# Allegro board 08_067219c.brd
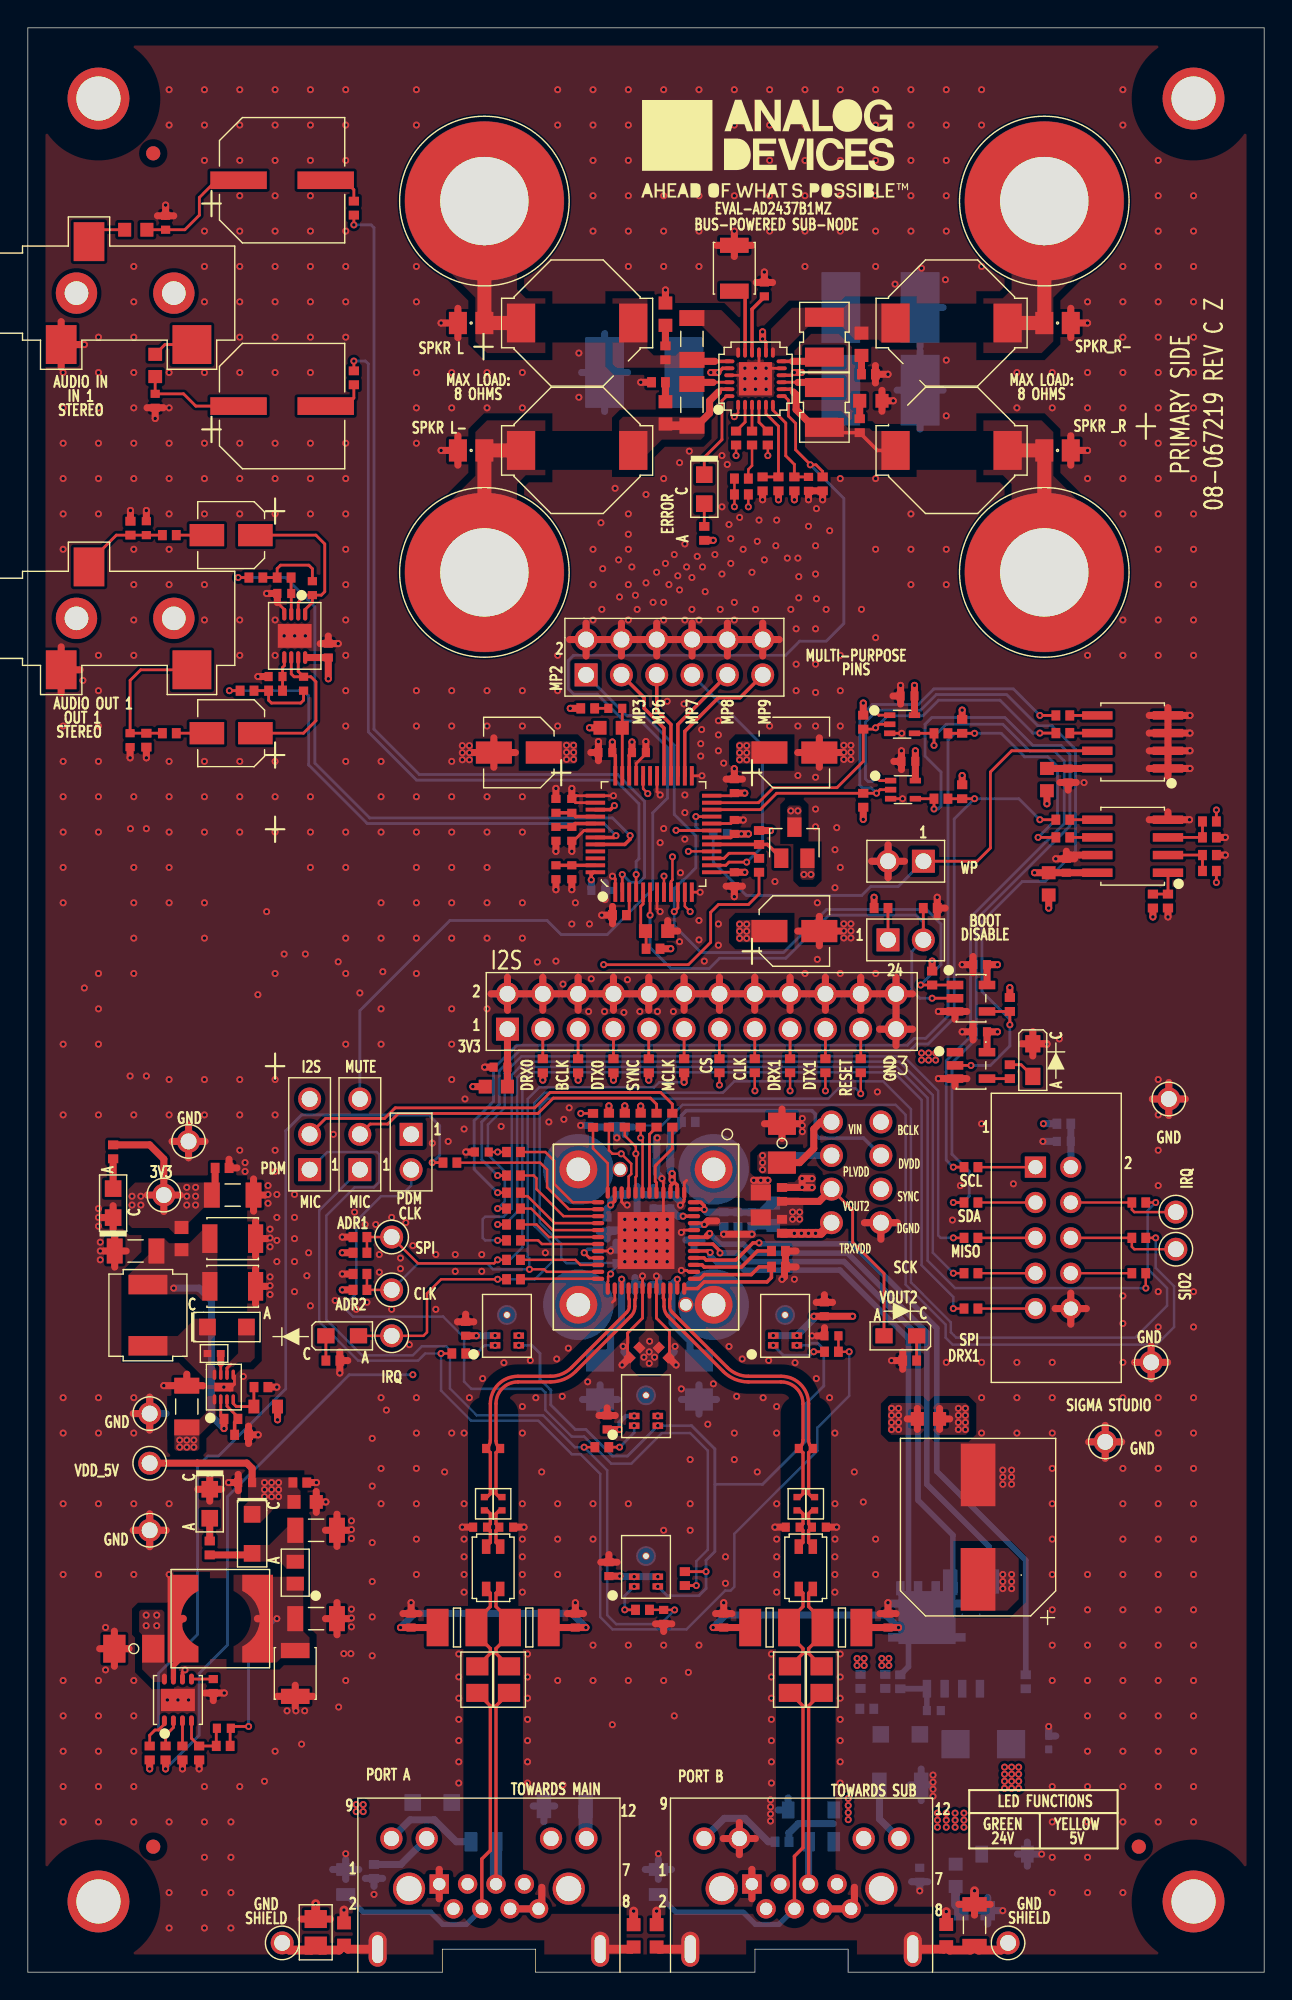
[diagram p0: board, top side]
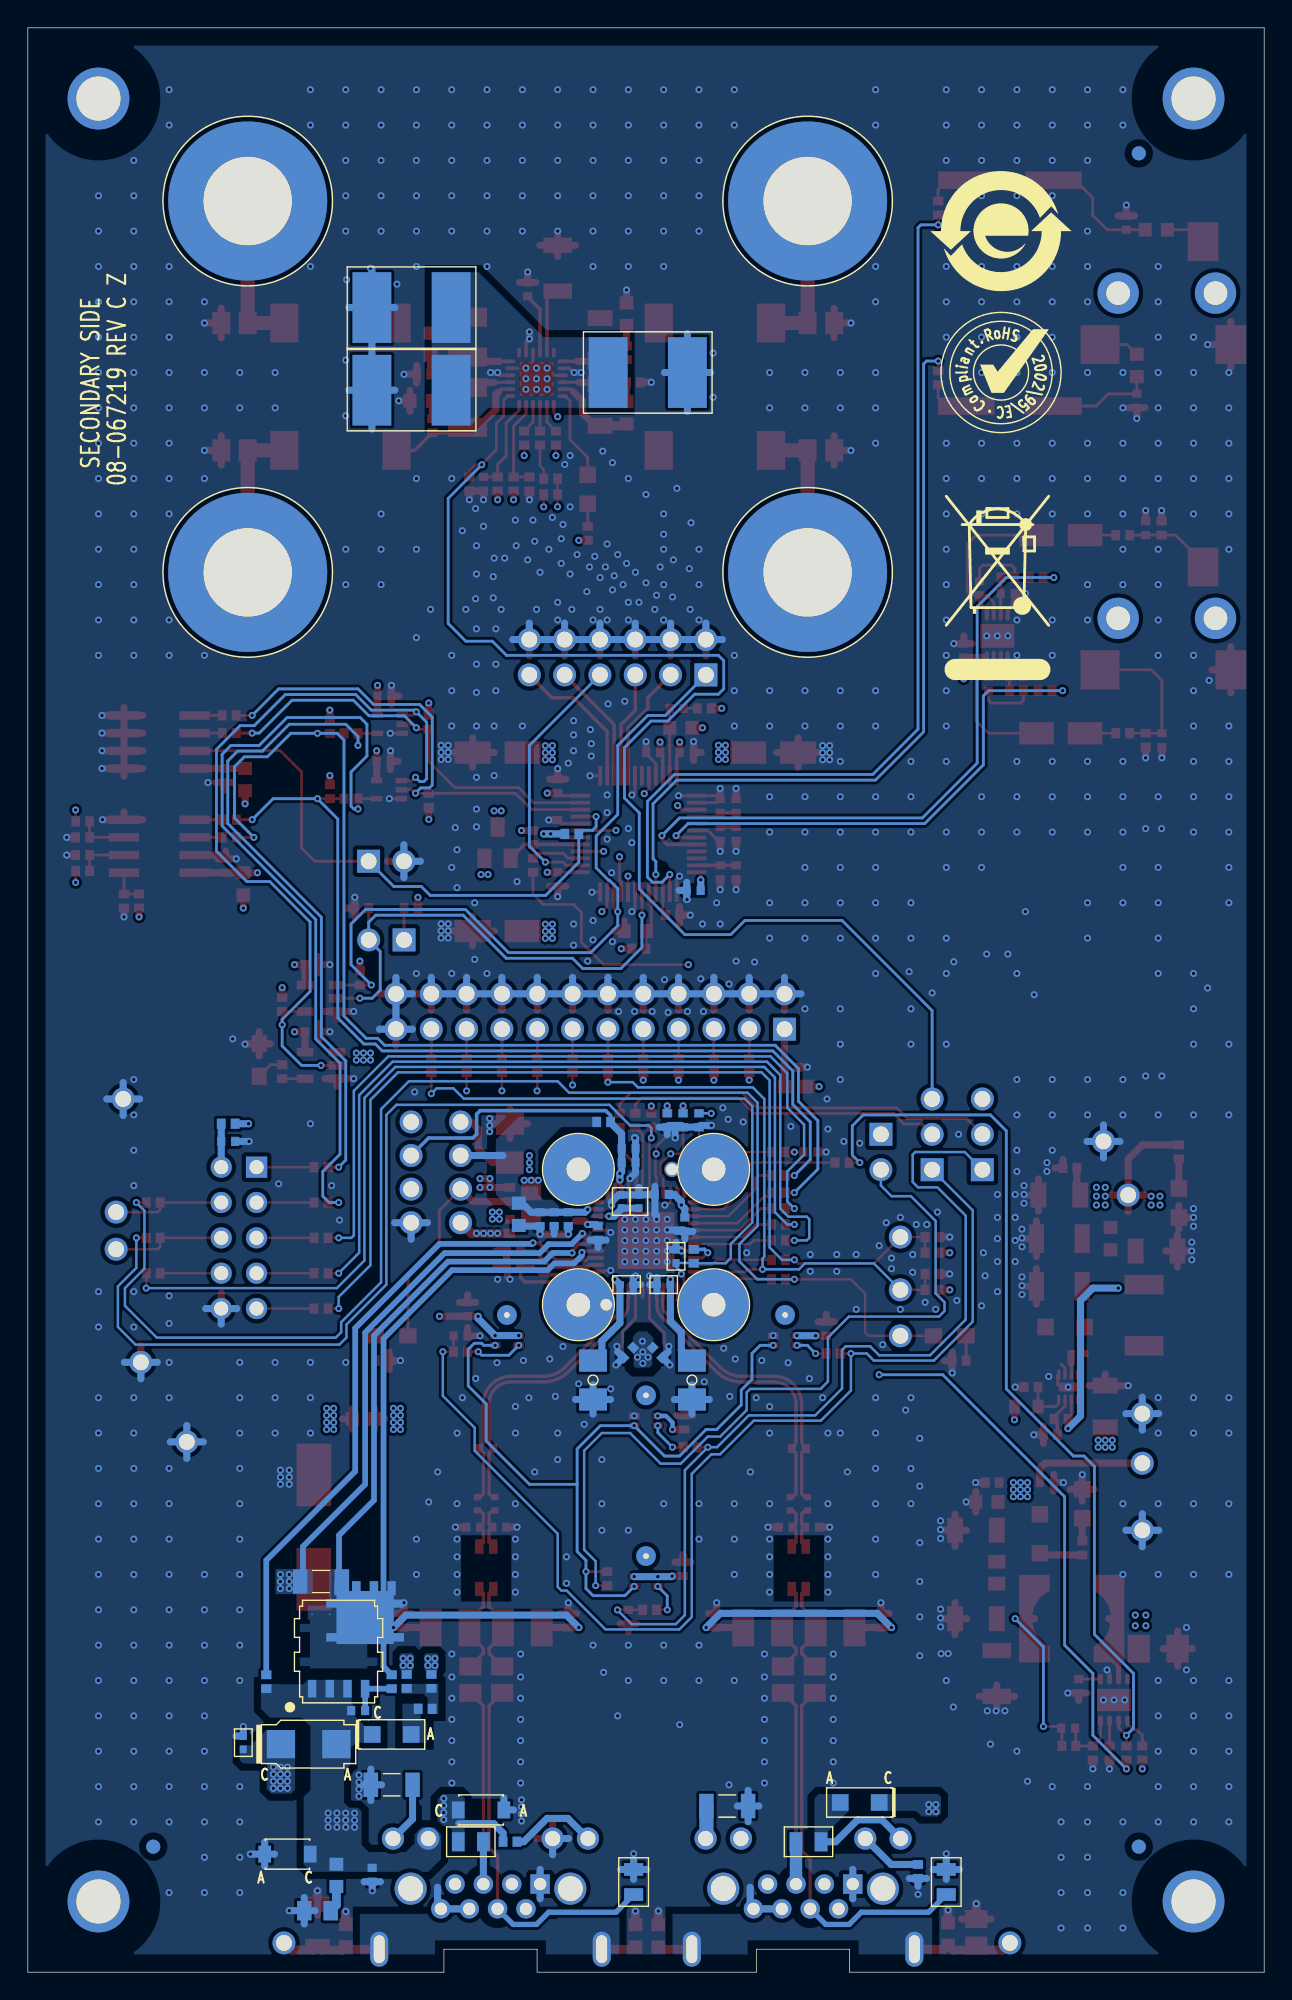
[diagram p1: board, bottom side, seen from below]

Outline 88.9 x 139.7 mm; copper layers: TOP, L2_GND, L3_PWR, L4_PWR, L5_GND, BOTTOM. Coordinates in mm from the lower left corner of the outline.
Outline path: 0,139.7 0,0 29.8,0 29.8,1.65 36.5,1.65 36.5,0 52.28,0 52.28,1.65 58.98,1.65 58.98,0 88.9,0 88.9,139.7 0,139.7

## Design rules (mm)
constraint set DEFAULT: min track width 0.203
net group AD243X_A: nets AD243X_AN AD243X_AP
net group AD243X_B: nets AD243X_BN AD243X_BP
net group DP1: nets UNNAMED_15_CAP_I9_N2 UNNAMED_15_CAP_I13_N1
net group DP2: nets UNNAMED_15_CAP_I95_N1 UNNAMED_15_CAP_I96_N1
net group DP3: nets UNNAMED_16_CAP_I13_N1 UNNAMED_16_CAP_I15_N2
net group DP4: nets UNNAMED_16_CAP_I69_N1 UNNAMED_16_CAP_I70_N1
net group DP5: nets UNNAMED_15_CAP_I95_N2 UNNAMED_15_CAP_I96_N2
net group DP6: nets UNNAMED_16_CAP_I69_N2 UNNAMED_16_CAP_I70_N2

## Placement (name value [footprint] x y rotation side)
A1  M24512-RMN6TP  [SO8]  79.44 88.39 90 top
A2  BD28623MUV-E2  [QFN24_4X4_PAD2_4X2_4]  52.32 114.49 0 top
A3  M24512-RMN6TP  [SO8]  79.44 80.9 90 top
C1  1uF  [C1206]  11.43 40.64 270 top
C2  0.1uF  [C0402]  45.7 59.18 180 bottom
C3  27pF  [C0402]  32.64 58.93 0 top
C4  4.7NF  [C0402]  45.7 58.17 0 bottom
C5  27pF  [C0402]  40.64 61.21 90 bottom
C6  27pF  [C0402]  41.78 61.21 90 bottom
C7  0.1uF  [C0402]  52.07 54.1 270 bottom
C8  27pF  [C0402]  42.93 61.21 90 bottom
C9  4.7NF  [C0402]  51.05 54.1 90 bottom
C10  4.7uF  [C0603]  53.59 54.45 90 bottom
C11  0.1uF  [C0402]  50.04 54.1 270 bottom
C12  10uF  [C1206H71]  54.23 59.56 270 top
C13  0.1uF  [C0402H22]  46.23 55.37 90 bottom
C14  0.1uF  [C0402H22]  44.96 55.37 90 bottom
C15  0.1uF  [C0402]  41.66 53.72 270 bottom
C16  0.1uF  [C0402]  43.31 55.88 0 bottom
C17  0.1uF  [C0402H22]  42.29 51.43 270 bottom
C18  6.8uF  [C0805]  52.7 55.13 270 top
C19  0.1uF  [C0402]  47.9 53.1 270 bottom
C20  0.1uF  [C0402]  45.72 44.52 315 bottom
C21  0.1uF  [C0402]  43.62 44.52 225 bottom
C22  4.7NF  [C0402]  45.72 44.52 135 top
C23  4.7NF  [C0402]  43.62 44.52 45 top
C24  12pF  [C0402]  33.46 37.63 0 top
C25  4.7uF  [C1206H71]  7.62 23.24 0 top
C27  4.7NF  [C0402]  13.34 20.56 90 top
C28  0.1uF  [C0402H22]  13.39 44.45 0 top
C29  27pF  [C0402]  32.52 31.98 180 top
C30  27pF  [C0402]  34.4 31.98 180 top
C31  0.033uF  [C0402]  39.37 25.26 90 top
C32  0.033uF  [C0402]  27.56 25.26 90 top
C33  0.01uF  [C0805H53]  32.32 21.02 270 top
C34  0.01uF  [C0805H53]  34.6 21.02 270 top
C35  10UF  [C1210-2]  14.73 52.7 180 top
C36  10UF  [C1210-2]  14.73 49.28 180 top
C37  10pF  [C0402]  14.1 17.53 0 top
C38  10UF  [C1210-2]  19.23 21.46 90 top
C39  22uF  [C1206]  20.73 25.4 180 top
C40  22uF  [C1206]  20.73 31.75 180 top
C41  4.7uF  [C0603]  19.94 33.79 180 top
C42  0.033uF  [C0402]  15.63 35.18 0 top
C43  4.7uF  [C1206H71]  48.26 42.55 90 bottom
C44  27pF  [C0402]  56.88 31.98 0 top
C46  0.1uF  [C0603]  66.71 6.96 270 bottom
C48  27pF  [C0402]  55 31.98 0 top
C50  0.01uF  [C0402]  65.15 18.8 180 bottom
C51  0.1uF  [C0402]  74.68 79.49 90 top
C53  0.033uF  [C0402]  64.14 7 270 bottom
C55  100pF  [C0402]  9.91 125.69 90 top
C56  100pF  [C0402]  9.16 112.9 270 top
C57  47uF  [CAPSML335W335H250]  18.28 128.75 0 top
C58  47uF  [CAPSML335W335H250]  18.28 112.52 0 top
C61  0.01uF  [C0805H53]  57.08 21.02 270 top
C62  0.1uF  [C0402]  41.66 39.5 90 top
C63  0.1uF  [C0402]  57.28 47.62 90 top
C64  0.1uF  [C0402]  31.48 46.23 90 top
C65  0.1uF  [C0402]  41.78 28.96 90 top
C66  33pF  [C0402]  57.78 45.72 0 top
C67  33pF  [C0402]  45.72 25.53 90 top
C69  0.1uF  [C0402]  74.8 85.98 270 top
C73  0.1uF  [C0402]  21.6 94.95 90 top
C74  150pF  [C0402]  18.44 99.06 180 top
C75  150pF  [C0402]  17.81 93.09 180 top
C76  470pF  [C0402]  20.46 99.44 270 top
C77  470pF  [C0402]  19.83 92.58 90 top
C78  1uF  [C0603]  45.21 74.8 180 top
C79  0.1uF  [C0402]  33.99 65.02 180 top
C80  0.1uF  [C0402]  74.49 59.69 180 bottom
C81  47uF  [CPLSMSQ169H240]  14.62 103.25 180 top
C82  47uF  [CPLSMSQ169H240]  14.62 89.02 180 top
C83  2.2NF  [C0402]  8.52 103.75 90 top
C84  2.2NF  [C0402]  7.36 88.52 270 top
C85  0.1uF  [C0402H22]  43.18 49.4 180 bottom
C86  4.7uF  [C1206H71]  41.15 42.55 90 bottom
C87  0.01uF  [C0805H53]  20.7 2.86 90 top
C88  12pF  [C0402]  55.94 37.63 180 top
C89  0.1uF  [C0402H22]  45.85 49.4 0 bottom
C90  0.1uF  [C0402]  56.13 106.93 270 top
C91  47uF  [CPLSMSQ409H413]  68.33 31.98 90 top
C92  0.1uF  [C0402H22]  73.41 16.49 270 bottom
C93  0.033uF  [C0402]  50.04 25.26 270 top
C94  0.033uF  [C0402]  61.85 25.26 90 top
C95  0.01uF  [C0805H53]  54.8 21.02 270 top
C96  10uF  [CAPSML169W169H217]  55.12 87.63 0 top
C97  10uF  [CAPSML169W169H217]  35.31 87.63 180 top
C98  0.1uF  [C0402]  39.12 79.03 270 top
C99  0.1uF  [C0402]  50.8 82.28 90 top
C100  10uF  [C0402]  37.97 79.03 270 top
C101  0.1uF  [C0402]  41.02 77.72 0 bottom
C102  0.1uF  [C0402]  39.12 83.8 90 top
C103  0.1uF  [C0402]  41.53 87.63 180 top
C104  10uF  [C0402]  37.97 83.8 90 top
C105  0.1uF  [C0402]  43.94 87.63 0 top
C106  10uF  [CAPSML169W169H217]  55.12 74.8 0 top
C107  0.1uF  [C0402]  50.8 78.53 270 top
C108  0.056uF  [C0402]  42.24 90.8 180 top
C109  0.1uF  [C0402]  50.8 85.22 90 top
C110  3.3NF  [C0603]  41.94 89.41 180 top
C111  10uF  [C0402]  37.97 81.79 270 top
C112  0.1uF  [C0402]  68.47 72.39 180 top
C113  0.1uF  [C0402]  39.12 81.79 270 top
C114  3.3uF  [C1206]  47.75 112.61 270 top
C115  3.3UF  [C1210H110]  57.28 112.43 90 top
C116  10uF  [C2220-1]  61.31 113.66 0 bottom
C117  10uF  [C2220-1]  44.32 114.94 180 bottom
C118  3.3UF  [C1210H110]  57.28 117.47 270 top
C119  680pF  [C0603]  45.85 112.04 270 top
C120  680pF  [C0603]  45.85 119.13 90 top
C121  3.3uF  [C1206]  47.75 117.35 270 top
C122  680pF  [C0603]  59.94 116.96 90 top
C123  680pF  [C0603]  60.62 112.9 0 top
C124  10UF  [C1210-2]  50.8 122.43 90 top
C125  10uF  [C2220-1]  61.31 119.6 180 bottom
C126  0.68uF  [C0805H60]  31.88 109.34 180 top
C127  0.68uF  [C0805H60]  31.88 118.49 0 top
C128  0.68uF  [C0805H60]  74.04 118.49 0 top
C129  0.68uF  [C0805H60]  74.04 109.34 180 top
C130  0.1uF  [C0402]  52.96 120.9 90 top
C131  22uF  [C1206]  7.75 51.82 0 top
C132  22uF  [C1206]  14.73 55.83 180 top
C133  0.1uF  [C0402]  63.32 87 180 top
C134  0.1uF  [C0402]  63.25 91.69 180 top
C135  0.1uF  [C0402]  68.47 67.56 180 top
D1  PMEG6010CEH,115  [SOD123F]  16.13 31.5 270 top
D2  NRVTSA3100ET3G  [SMA]  68.71 16.38 180 bottom
D3  PMEG6010CEH,115  [SOD123F]  62.74 17.08 180 bottom
D4  TPSMF4L30A  [SOD123FL]  70.23 8.48 0 bottom
D5  PMEG6010CEH,115  [SOD123F]  14.32 46.35 0 top
D6  PMEG6010CEH,115  [SOD123F]  29.08 12.19 0 bottom
D7  TPSMF4L30A  [SOD123FL]  56.31 11.66 180 bottom
DS1  SML-LXT0805GW-TR  [LXT0805]  6.13 55.26 90 top
DS2  HSMS-C170  [LED0805]  22.61 45.72 0 top
DS3  HSMG-C170  [LED0805]  62.74 45.72 180 top
DS4  HSMS-C170  [LED0805]  72.26 65.53 270 top
DS5  SML-LXT0805GW-TR  [LXT0805]  13.08 33.66 270 top
DS6  SML-LXT0805YW-TR  [LXT0805]  48.64 106.55 270 top
E1  600OHM AT 100MEGHZ  [L0603-2]  19.23 28.7 90 top
E2  600OHMS  [L0603]  7.76 125.19 0 top
E3  600OHMS  [L0603]  9.16 115.44 270 top
E4  600OHMS  [L0603]  64.76 39.75 180 top
E9  600OHMS  [L0603]  73.28 85.69 90 top
E10  600OHMS  [L0603]  33.69 63.63 180 top
E12  470OHM AT 100MEGHZ  [L0603]  22.73 2.74 270 top
E13  470OHM AT 100MEGHZ  [L0603]  43.56 2.61 270 top
E14  470OHM AT 100MEGHZ  [L0603]  45.21 2.61 270 top
E15  470OHM AT 100MEGHZ  [L0603]  66.04 2.63 270 top
E16  470OHM AT 100MEGHZ  [L0603]  11.05 52.7 90 top
E17  600OHMS  [L0603]  73.41 78.19 90 top
FL1  ACT1210L-101-2P-TL00  [FLSML154W98H98]  33.46 29.05 270 top
FL2  ACT1210L-101-2P-TL00  [FLSML154W98H98]  55.94 29.05 270 top
L1  180NH  [L0402-3]  32.83 33.66 270 top
L2  180NH  [L0402-3]  34.1 33.66 270 top
L3  3.3UH  [L0805H57]  22.86 6.48 90 bottom
L4  3.3UH  [L0805H57]  32.77 9.37 180 bottom
L6  100UH  [LSMSQ228H118_A]  13.84 25.4 0 top
L10  180NH  [L0402-3]  55.3 33.66 270 top
L11  180NH  [L0402-3]  56.57 33.66 270 top
L12  3.3UH  [L0805H57]  45.34 6.48 90 bottom
L13  3.3UH  [L0805H57]  57.04 9.37 0 bottom
L14  15uH  [INDSUMCDRH8D43]  39.5 109.34 180 top
L15  15uH  [INDSUMCDRH8D43]  39.5 118.49 180 top
L16  15uH  [INDSUMCDRH8D43]  66.42 118.49 0 top
L17  15uH  [INDSUMCDRH8D43]  66.42 109.34 0 top
L18  4.7UH  [LSML213W201H59]  8.64 47.2 90 top
NOREF  -  []  46.18 59.63 0 top
NOREF#2  -  [unnamed#2]  83.82 134.62 0 top
NOREF#3  -  []  88.9 0 0 top
NOREF#4  -  []  53.73 130.69 0 top
NOREF#5  -  []  -12.95 94.11 0 top
NOREF#6  -  []  0 139.7 0 top
NOREF#7  -  []  -105.41 -135.39 0 top
NOREF#8  -  []  275.59 328.16 0 top
NOREF#9  -  [unnamed#2]  83.82 5.08 0 top
NOREF#10  -  []  44.65 -89.37 0 top
NOREF#11  -  []  71.43 131.87 0 top
NOREF#12  -  []  5.08 5.08 0 top
NOREF#13  -  []  5.08 5.08 0 top
NOREF#14  -  [unnamed#2]  9.02 9.02 90 top
NOREF#15  -  []  37.16 0 0 top
NOREF#16  -  []  -105.41 -135.39 0 top
NOREF#17  -  []  27.43 -56.71 0 top
NOREF#18  -  []  81.66 19.93 0 top
NOREF#19  -  []  0 139.7 0 top
NOREF#20  -  []  165.48 123.83 0 top
NOREF#21  -  []  44.45 40.67 0 top
NOREF#22  -  []  11.12 -89.37 90 top
NOREF#23  -  [unnamed#2]  79.88 9.02 180 top
NOREF#24  -  []  -44.45 235.45 0 top
NOREF#25  -  []  -85.28 13.58 0 top
NOREF#26  -  [unnamed#2]  5.08 5.08 0 top
NOREF#27  -  []  64.77 -89.37 0 top
NOREF#28  -  [unnamed#2]  9.02 130.68 0 top
NOREF#29  -  [unnamed#2]  5.08 134.62 0 top
NOREF#30  -  []  33.15 1.65 0 top
NOREF#31  -  []  0 0 0 top
NOREF#32  -  []  24.53 -89.37 0 top
NOREF#33  -  []  -105.41 -135.39 0 top
NOREF#34  -  []  59.63 0 0 top
NOREF#35  -  []  88.9 0 90 top
NOREF#36  -  []  -105.41 -135.39 0 top
NOREF#37  -  []  153.42 178.93 0 top
NOREF#38  -  []  0 0 0 top
NOREF#39  -  []  27.79 183.9 0 top
NOREF#40  -  []  24.53 -79.46 0 top
NOREF#41  -  []  55.63 1.65 0 top
NOREF#42  -  []  44.75 -79.46 0 top
NOREF#43  -  [unnamed#2]  79.88 9.02 0 bottom
NOREF#44  -  [unnamed#2]  9.02 9.02 270 bottom
NOREF#45  -  [unnamed#2]  9.02 130.68 180 bottom
NOREF#46  -  []  18.92 114.94 180 bottom
NOREF#47  -  []  18.92 125.09 180 bottom
NOREF#48  -  []  9.91 109.73 180 bottom
P1  TSW-112-07-G-D  [CNTHMHDR2X12L1200W200H330]  34.49 67.75 0 top
P2  N2510-6002-RB  [CN3MN2510-6002RB]  72.45 57.84 270 top
P4  TSW-103-07-G-S  [CNTHMHDR1X3L300W98H343]  20.26 57.66 90 top
P5  TSW-106-07-G-D  [CNHDR2X6H330]  40.14 93.21 0 top
P6  TESTPAD  [TPC65D45]  57.78 58.67 0 top
P7  SJ-3523-SMT  [CNCUISJ-3523-SMT]  7 120.64 0 top
P8  TESTPAD  [TPC65D45]  57.78 61.09 180 top
P9  TESTPAD  [TPC65D45]  61.34 58.67 90 top
P10  TESTPAD  [TPC65D45]  57.78 53.85 0 top
P11  TESTPAD  [TPC65D45]  61.34 61.09 90 top
P12  TESTPAD  [TPC65D45]  61.34 56.26 0 top
P13  TESTPAD  [TPC65D45]  61.34 53.85 0 top
P14  TESTPAD  [TPC65D45]  26.16 52.82 0 top
P15  TESTPAD  [TPC65D45]  57.78 56.26 0 top
P16  TSW-102-07-G-S  [CNTHMHDR1X2L200W98H343]  27.56 60.2 270 top
P17  TESTPAD  [TPC65D45]  26.16 49.02 0 top
P18  TSW-102-07-G-S  [CNTHMHDR1X2L200W98H343]  64.4 79.82 180 top
P20  SJ-3523-SMT  [CNCUISJ-3523-SMT]  7 97.27 0 top
P21  RJE73-188-00210  [MRJE73-188-00XXX]  52.06 6.33 0 top
P22  TSW-102-07-G-S  [CNTHMHDR1X2L200W98H343]  61.85 74.17 0 top
P23  TSW-103-07-G-S  [CNTHMHDR1X3L300W98H343]  23.88 57.66 90 top
P27  RJE73-188-00210  [MRJE73-188-00XXX]  29.58 6.33 0 top
P39  TESTPAD  [TPC65D45]  11.56 59.69 0 top
P40  TESTPAD  [TPC65D45]  8.76 31.75 0 top
P41  TESTPAD  [TPC65D45]  77.47 38.1 0 top
P42  TESTPAD  [TPC65D45]  8.76 40.13 0 top
P43  TESTPAD  [TPC65D45]  82.55 51.94 270 top
P44  TESTPAD  [TPC65D45]  82.55 54.61 270 top
P45  111-2223-001  [CNEMERSON111-2223-001]  32.83 100.57 0 top
P46  111-2223-001  [CNEMERSON111-2223-001]  32.83 127.25 0 top
P47  111-2223-001  [CNEMERSON111-2223-001]  73.09 127.25 0 top
P48  111-2223-001  [CNEMERSON111-2223-001]  73.09 100.57 0 top
Q1  DMTH8012LPSQ-13  [POWERDI5060-8]  66.55 23.04 180 bottom
Q2  ZXTP25040DFLTA  [SOT23]  55.12 81.15 0 top
R1  24.9K  [R0603]  17.11 40.64 0 top
R2  31.6K  [R0402]  14.61 39.75 0 top
R3  10K  [R0402]  15.37 38.61 180 top
R4  0  [R0402]  47.5 61.09 0 bottom
R5  100K  [R0402]  64.89 76.45 180 top
R6  0  [R0402]  46.34 61.21 270 top
R7  0  [R0402]  45.21 61.21 270 top
R8  0  [R0402]  44.07 61.21 270 top
R9  33  [R0402]  42.93 61.21 270 top
R10  33  [R0402]  41.78 61.21 270 top
R11  33  [R0402]  40.64 61.2 270 top
R12  33  [R0402]  34.92 58.93 0 top
R13  0  [R0402]  34.92 51.18 180 top
R14  0  [R0402]  34.92 49.78 180 top
R15  0  [R0402]  30.35 58.17 0 top
R16  1K  [R0402]  6.13 58.94 90 top
R17  0  [R0402]  80.9 76.96 270 top
R18  0  [R0402]  54.23 55.88 270 top
R19  0  [R0402]  34.92 57.24 180 top
R20  0  [R0402]  34.92 56.01 180 top
R21  0  [R0402]  34.92 54.86 180 top
R22  33  [R0402]  34.92 53.72 180 top
R23  0  [R0402]  34.92 52.58 180 top
R24  100K  [R0402]  8.76 15.75 270 top
R25  0  [R0402]  74.42 81.53 180 top
R26  0  [R0402]  84.96 82.68 0 top
R27  0  [R0402]  11.12 15.75 90 top
R28  0  [R0402]  84.96 81.53 180 top
R29  100K  [R0402]  9.91 15.75 270 top
R30  0  [R0402]  74.42 82.8 180 top
R31  10K  [R0402]  23.88 52.82 0 top
R32  10K  [R0402]  23.88 50.16 0 top
R33  0  [R0402]  54.23 53.59 270 top
R34  10K  [R0402]  23.88 49.02 180 top
R35  1K  [R0402]  21.93 43.94 180 top
R36  1K  [R0402]  63.41 43.94 0 top
R37  120  [R1210]  30.86 24.76 180 top
R38  120  [R1210]  36.06 24.76 0 top
R39  10K  [R0402]  49.78 81.78 0 bottom
R40  56.2K  [R0402]  14.05 16.26 0 top
R41  10.2K  [R0402]  12.32 15.75 90 top
R42  10K  [R0402]  57.15 106.93 90 top
R43  10K  [R0402]  41.02 51.43 270 bottom
R44  10K  [R0402]  44.96 73.53 0 top
R45  12  [R0805]  68.07 4.42 0 bottom
R46  100K  [R0402]  19.56 35.18 180 top
R47  1K  [R0402]  13.08 30.48 270 top
R48  4.32K  [R0402]  16.76 42.04 180 top
R49  470  [R0402]  13.97 57.78 180 top
R51  10K  [R0402]  74.49 60.96 180 bottom
R52  0  [R0402]  47.24 28.28 270 top
R53  33  [R0402]  41.27 37.72 180 top
R54  33  [R0402]  57.78 44.58 0 top
R55  33  [R0402]  30.99 44.45 180 top
R56  33  [R0402]  44.2 26.03 0 top
R61  0  [R0402]  74.42 89.03 180 top
R62  0  [R0402]  74.42 90.3 180 top
R66  0  [R0402]  37.03 65.13 270 top
R67  0  [R0402]  39.57 65.13 270 top
R68  0  [R0402]  42.11 65.13 270 top
R69  0  [R0402]  44.65 65.13 270 top
R70  0  [R0402]  47.19 65.13 270 top
R71  0  [R0402]  49.73 65.13 270 top
R72  0  [R0402]  52.27 65.13 270 top
R73  18.2K  [R0402]  23.44 126.75 270 top
R74  0  [R0402]  54.81 65.13 270 top
R75  0  [R0402]  57.35 65.13 270 top
R76  0  [R0402]  59.89 65.13 270 top
R77  0  [R0402]  67.82 57.84 180 top
R78  0  [R0402]  67.82 55.3 180 top
R79  0  [R0402]  67.82 52.76 180 top
R80  0  [R0402]  67.82 50.22 180 top
R81  0  [R0402]  79.88 50.22 0 top
R82  0  [R0402]  67.82 47.68 180 top
R83  47K  [R0402]  52.83 106.93 270 top
R84  18.2K  [R0402]  23.44 114.55 90 top
R89  4.75K  [R0402]  16.4 100.2 0 top
R90  4.75K  [R0402]  15.76 92.08 0 top
R91  4.75K  [R0402]  18.43 100.2 0 top
R92  4.75K  [R0402]  17.81 92.08 0 top
R93  604  [R0402]  10.17 103.25 180 top
R94  604  [R0402]  10.17 89.02 180 top
R95  49.9K  [R0402]  7.38 103.75 90 top
R96  49.9K  [R0402]  8.52 88.52 270 top
R97  0  [R0402]  84.96 79.12 0 top
R98  0  [R0402]  62.74 20.87 270 bottom
R99  0  [R0402]  71.75 20.87 270 bottom
R100  100K  [R0402]  53.98 50.67 180 top
R101  100K  [R0402]  53.98 51.82 180 top
R102  0.05  [R1206]  67.82 28.07 0 bottom
R103  120  [R1210]  53.34 24.76 0 top
R104  120  [R1210]  58.54 24.76 180 top
R105  0  [R0402]  59.88 20.89 90 bottom
R106  100  [R0402]  60.32 18.92 180 bottom
R107  0  [R0402]  61.66 20.89 90 bottom
R108  0  [R1206]  68.07 3.37 270 top
R109  18.2K  [R0402]  42.55 75.95 0 top
R110  33  [R0402]  52.58 79.53 90 top
R111  475  [R0402]  40.26 90.8 180 top
R112  1K  [R0402]  52.58 81.53 90 top
R113  10K  [R0402]  61.35 76.45 180 top
R114  47K  [R0402]  53.98 106.93 90 top
R115  330  [R0402]  48.64 103.38 90 top
R116  10K  [R0402]  55.12 106.93 270 top
R117  0  [R0402]  79.88 55.3 0 top
R118  0  [R0402]  50.93 110.23 90 top
R119  0  [R0402]  52.07 110.23 90 top
R120  0  [R0402]  53.21 110.23 90 top
R121  5.6  [R0402]  45.35 114.23 0 top
R122  5.6  [R0402]  45.85 116.35 90 top
R123  5.6  [R0402]  60.44 114.81 180 top
R124  5.6  [R0402]  59.82 111.11 90 top
R125  0  [R0402]  79.88 52.76 0 top
R126  0  [R0402]  51.31 106.17 0 top
R127  0  [R0402]  51.31 107.31 0 top
R128  10K  [R0402]  23.88 51.69 180 top
R129  10K  [R0402]  65.02 71.43 90 top
R130  0  [R0402]  84.96 80.26 180 top
R131  0  [R0402]  81.98 76.96 90 top
R132  2.55K  [R0402]  60.07 84.2 270 top
R133  2.55K  [R0402]  60.07 89.81 90 top
R134  2.55K  [R0402]  70.61 69.53 90 top
R135  330  [R0402]  70.61 64.7 90 top
R136  0  [R0402]  65.66 84.31 180 top
R137  0  [R0402]  65.66 89.01 180 top
R138  2.55K  [R0402]  67.18 89.51 90 top
R139  2.55K  [R0402]  67.18 84.81 90 top
R140  2.74K  [R1206]  38.61 11.94 180 bottom
R141  365  [R0402]  24.89 7.24 90 bottom
R142  365  [R0402]  54.23 9.37 180 bottom
R143  2.74K  [R1206]  62.74 13.46 0 bottom
TP1  TESTPAD  [TPC65D45]  9.78 55.83 90 top
TP2  TESTPAD  [TPC65D45]  8.76 36.57 180 top
TP3  TESTPAD  [TPC65D45]  18.29 2.1 90 top
TP4  TESTPAD  [TPC65D45]  70.48 2.1 90 top
TP9  TESTPAD  [TPC65D45]  26.16 45.72 270 top
TP10  TESTPAD  [TPC65D45]  80.77 43.81 0 top
TP11  TESTPAD  [TPC65D45]  82.04 62.74 270 top
U1  IM69D120V01XTSA1  [LGA-CAV5-1]  54.45 46.44 180 top
U2  LT3502AEDC#TRMPBF  [DFN8_2X2_PAD1_37X0_64]  14.1 42.04 0 top
U3  IM69D120V01XTSA1  [LGA-CAV5-1]  34.45 46.44 180 top
U4  IM69D120V01XTSA1  [LGA-CAV5-1]  44.45 29.12 180 top
U5  IM69D120V01XTSA1  [LGA-CAV5-1]  44.45 40.67 180 top
U7  AD2437  [QFN48_7X7_PAD4_1X4_1]  44.45 52.82 180 top
U8  ADP2360ACPZ  [DFN8_3X3_PAD2_44X1_6]  10.79 19.56 0 top
U9  SN74LVC1G08QDBVRQ1  [SOT23-5L-2]  67.82 69.98 270 top
U10  ADAU1701JSTZ  [48LQFP]  44.99 81.78 0 top
U12  SN74CB3T1G125DCKR  [SC70-5]  62.93 84.96 270 top
U13  ADA4661-2ACPZ  [QFN8_3X3_PAD2_44X1_7]  19.19 96.01 180 top
U14  SN74CB3T1G125DCKR  [SC70-5]  62.86 89.66 270 top
U15  SN74LVC1G04DBVR  [SOT23-5L-2]  67.82 65.15 270 top

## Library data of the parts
A1 A3 = ICM24512: Tolerance: N/A; User Part Number: UPN; alternate symbols: (); part number: ICM24512_SM-M24512-RMN6TP,E041427,SO8; tolerance: N/A
A2 = ICBD28623MUV: Tolerance: N/A; User Part Number: UPN; alternate symbols: (); part number: ICBD28623MUV_SM-BD28623MUV-E2,E051667,QFN24_4X4_PAD2_4X2_4; tolerance: N/A
C1 = CAP: User Part Number: UPN; Tolerance: 10; alternate symbols: (C1206L); part number: CAP_SM-1UF,50V,10,E021800,C1206; tolerance: 10
C2 C7 C11 C15 C16 C19-C21 C51 C62-C65 C69 C73 C79 C80 C90 C98 C99 C101-C103 C105 C107 C109 C112 C113 C130 C133-C135 = CAP: User Part Number: UPN; Tolerance: 10; alternate symbols: (C0402L); part number: CAP_SM-0.1UF,25V,10,E025708,C0402; tolerance: 10
C3 C5 C6 C8 C29 C30 C44 C48 = CAP: User Part Number: UPN; Tolerance: 5; alternate symbols: (C0402L); part number: CAP_SM-27PF,50V,5,E033384,C0402; tolerance: 5
C4 C9 C22 C23 C27 = CAP: User Part Number: UPN; Tolerance: 10; alternate symbols: (C0402L); part number: CAP_SM-4.7NF,16V,10,E042800,C0402; tolerance: 10
C10 C41 = CAP: User Part Number: UPN; Tolerance: 10; alternate symbols: (C0603L); part number: CAP_SM-4.7UF,35V,10,E039350,C0603; tolerance: 10
C12 = CAP: Tolerance: 10; User Part Number: UPN; alternate symbols: (C1206L); part number: CAP_SM-10UF,50V,10,E026881,C1206H71; tolerance: 10
C13 C14 C17 C28 C85 C89 C92 = CAP: Tolerance: 10; User Part Number: UPN; alternate symbols: (); part number: CAP_SM-0.1UF,50V,10,E018452,C0402H22; tolerance: 10
C18 = CAP: User Part Number: UPN; Tolerance: 10; alternate symbols: (C0805L); part number: CAP_SM-6.8UF,6.3V,10,E000565,C0805; tolerance: 10
C24 C88 = CAP: User Part Number: UPN; Tolerance: 5; alternate symbols: (C0402L); part number: CAP_SM-12PF,50V,5,E034633,C0402; tolerance: 5
C25 C43 C86 = CAP: Tolerance: 10; User Part Number: UPN; alternate symbols: (); part number: CAP_SM-4.7UF,50V,10,E026699,C1206H71; tolerance: 10
C31 C32 C42 C53 C93 C94 = CAP: User Part Number: UPN; Tolerance: 10; alternate symbols: (C0402L); part number: CAP_SM-0.033UF,50V,10,E019776,C0402; tolerance: 10
C33 C34 C61 C87 C95 = CAP: Tolerance: 10; User Part Number: UPN; alternate symbols: (); part number: CAP_SM-0.01UF,500V,10,E023443,C0805H53; tolerance: 10
C35 C36 C38 C124 = CAP: Tolerance: 10; User Part Number: UPN; alternate symbols: (C1210H106); part number: CAP_SM-10UF,25V,10,E013830,C1210-2; tolerance: 10
C37 = CAP: User Part Number: UPN; Tolerance: 5; alternate symbols: (C0402L); part number: CAP_SM-10PF,50V,5,E035301,C0402; tolerance: 5
C39 C40 C131 C132 = CAP: User Part Number: UPN; Tolerance: 10; alternate symbols: (C1206L); part number: CAP_SM-22UF,16V,10,E026209,C1206; tolerance: 10
C46 = CAP: User Part Number: UPN; Tolerance: 10; alternate symbols: (C0603L); part number: CAP_SM-0.1UF,50V,10,E011865,C0603; tolerance: 10
C50 = CAP: User Part Number: UPN; Tolerance: 10; alternate symbols: (C0402L); part number: CAP_SM-0.01UF,50V,10,E019413,C0402; tolerance: 10
C55 C56 = CAP: User Part Number: UPN; Tolerance: 5; alternate symbols: (C0402L); part number: CAP_SM-100PF,50V,5,E022402,C0402; tolerance: 5
C57 C58 = CAPP: User Part Number: UPN; Tolerance: 20; alternate symbols: (); part number: CAPP_SM-47UF,25V,20,E000682,CAPSML335W335H250; tolerance: 20
C66 C67 = CAP: User Part Number: UPN; Tolerance: 5; alternate symbols: (C0402L); part number: CAP_SM-33PF,50V,5,E027128,C0402; tolerance: 5
C74 C75 = CAP: User Part Number: UPN; Tolerance: 10; alternate symbols: (C0402L); part number: CAP_SM-150PF,50V,10,E033997,C0402; tolerance: 10
C76 C77 = CAP: User Part Number: UPN; Tolerance: 10; alternate symbols: (C0402L); part number: CAP_SM-470PF,25V,10,E012313,C0402; tolerance: 10
C78 = CAP: User Part Number: UPN; Tolerance: 10; alternate symbols: (C0603L); part number: CAP_SM-1UF,16V,10,E020111,C0603; tolerance: 10
C81 C82 = CAPP: Tolerance: 20; User Part Number: UPN; alternate symbols: (); part number: CAPP_SM-47UF,6.3V,20,E014836,CPLSMSQ169H240; tolerance: 20
C83 C84 = CAP: User Part Number: UPN; Tolerance: 20; alternate symbols: (C0402L); part number: CAP_SM-2.2NF,25V,20,E042791,C0402; tolerance: 20
C91 = CAPP: Tolerance: 20; User Part Number: UPN; alternate symbols: (); part number: CAPP_SM-47UF,50V,20,E017660,CPLSMSQ409H413; tolerance: 20
C96 C97 C106 = CAPP: Tolerance: 20; User Part Number: UPN; alternate symbols: (); part number: CAPP_SM-10UF,16V,20,E005931,CAPSML169W169H217; tolerance: 20
C100 C104 C111 = CAP: User Part Number: UPN; Tolerance: 20; alternate symbols: (C0402L); part number: CAP_SM-10UF,10V,20,E020928,C0402; tolerance: 20
C108 = CAP: User Part Number: UPN; Tolerance: 0.1; alternate symbols: (C0402L); part number: CAP_SM-0.056UF,16V,0.1,E019786,C0402; tolerance: 0.1
C110 = CAP: User Part Number: UPN; Tolerance: 20; alternate symbols: (C0603L); part number: CAP_SM-3.3NF,16V,20,E042849,C0603; tolerance: 20
C114 C121 = CAP: User Part Number: UPN; Tolerance: 10; alternate symbols: (C1206L); part number: CAP_SM-3.3UF,16V,10,E000196,C1206; tolerance: 10
C115 C118 = CAP: Tolerance: 20; User Part Number: UPN; alternate symbols: (); part number: CAP_SM-3.3UF,50V,20,E042926,C1210H110; tolerance: 20
C116 C117 C125 = CAP: Tolerance: 10; User Part Number: UPN; alternate symbols: (); part number: CAP_SM-10UF,50V,10,E007065,C2220-1; tolerance: 10
C119 C120 C122 C123 = CAP: User Part Number: UPN; Tolerance: 5; alternate symbols: (C0603L); part number: CAP_SM-680PF,50V,5,E000431,C0603; tolerance: 5
C126-C129 = CAP: Tolerance: 5; User Part Number: UPN; alternate symbols: (); part number: CAP_SM-0.68UF,25V,5,E018577,C0805H60; tolerance: 5
D1 D3 D5 D6 = DIOSCHOTTKY: Tolerance: N/A; User Part Number: UPN; alternate symbols: (); part number: DIOSCHOTTKY_SM-PMEG6010CEH,115,60V,N/A,E052090,SOD123F; tolerance: N/A
D2 = DIOSCHOTTKY: User Part Number: UPN; Tolerance: N/A; alternate symbols: (); part number: DIOSCHOTTKY_SM-NRVTSA3100ET3G,100V,N/A,E044405,SMA; tolerance: N/A
D4 D7 = DIOZNR: User Part Number: UPN; Tolerance: N/A; alternate symbols: (); part number: DIOZNR_SM-TPSMF4L30A,30V,N/A,E047953,SOD123FL; tolerance: N/A
DS1 DS5 = DIOLED: Tolerance: N/A; User Part Number: UPN; alternate symbols: (); part number: DIOLED_SM-SML-LXT0805GW-TR,N/A,N/A,E005318,LXT0805; tolerance: N/A
DS2 DS4 = DIOLED: Tolerance: N/A; User Part Number: UPN; alternate symbols: (); part number: DIOLED_SM-HSMS-C170,N/A,N/A,E019221,LED0805; tolerance: N/A
DS3 = DIOLED: Tolerance: N/A; User Part Number: UPN; alternate symbols: (); part number: DIOLED_SM-HSMG-C170,N/A,N/A,E019220,LED0805; tolerance: N/A
DS6 = DIOLED: Tolerance: N/A; User Part Number: UPN; alternate symbols: (); part number: DIOLED_SM-SML-LXT0805YW-TR,N/A,N/A,E005351,LXT0805; tolerance: N/A
E1 = FERRITE: Tolerance: 25; User Part Number: UPN; alternate symbols: (); part number: FERRITE_SM-600OHM AT 100MEGHZ,25,E038446,L0603-2; tolerance: 25
E2-E4 E9 E10 E17 = FERRITE: User Part Number: UPN; Tolerance: 25; alternate symbols: (L0603L); part number: FERRITE_SM-600OHMS,25,E007179,L0603; tolerance: 25
E12-E16 = FERRITE: User Part Number: UPN; Tolerance: 25; alternate symbols: (L0603L); part number: FERRITE_SM-470OHM AT 100MEGHZ,25,E044359,L0603; tolerance: 25
FL1 FL2 = FLTR4P_V7: User Part Number: UPN; Tolerance: N/A; alternate symbols: (); part number: FLTR4P_V7_SM-ACT1210L-101-2P-TL00,E033324,FLSML154W98H98; tolerance: N/A
L1 L2 L10 L11 = IND: Tolerance: 5; User Part Number: UPN; alternate symbols: (); part number: IND_SM-180NH,5,E034614,L0402-3; tolerance: 5
L3 L4 L12 L13 = IND: User Part Number: UPN; Tolerance: 20; alternate symbols: (); part number: IND_SM-3.3UH,20,E033480,L0805H57; tolerance: 20
L6 = IND: User Part Number: UPN; Tolerance: 30; alternate symbols: (); part number: IND_SM-100UH,30,E043716,LSMSQ228H118_A; tolerance: 30
L14-L17 = IND: Tolerance: 30; User Part Number: UPN; alternate symbols: (); part number: IND_SM-15UH,30,E005329,INDSUMCDRH8D43; tolerance: 30
L18 = IND: User Part Number: UPN; Tolerance: 20; alternate symbols: (); part number: IND_SM-4.7UH,20,E039845,LSML213W201H59; tolerance: 20
P1 = CN24P_ODD_EVEN: User Part Number: UPN; Tolerance: N/A; alternate symbols: (); part number: CN24P_ODD_EVEN_TH-TSW-112-07-G-D,E054617,CNTHMHDR2X12L1200W200H330; tolerance: N/A
P2 = CN10P: Tolerance: N/A; User Part Number: UPN; alternate symbols: (); part number: CN10P_TH-N2510-6002-RB,E005954,CN3MN2510-6002RB; tolerance: N/A
P4 P23 = CN3P: User Part Number: UPN; Tolerance: N/A; alternate symbols: (); part number: CN3P_TH-TSW-103-07-G-S,E042653,CNTHMHDR1X3L300W98H343; tolerance: N/A
P5 = CN12P: User Part Number: UPN; Tolerance: N/A; alternate symbols: (); part number: CN12P_TH-TSW-106-07-G-D,E016473,CNHDR2X6H330; tolerance: N/A
P6 P8-P15 P17 P39-P44 TP1-TP4 TP9-TP11 = NCTESTPAD: Tolerance: N/A; User Part Number: UPN; alternate symbols: (); part number: NCTESTPAD_TH-TESTPAD,E013404,TPC65D45; tolerance: N/A
P7 P20 = CN3P: Tolerance: N/A; User Part Number: UPN; alternate symbols: (); part number: CN3P_SM-SJ-3523-SMT,E008203,CNCUISJ-3523-SMT; tolerance: N/A
P16 P18 P22 = CN2P: User Part Number: UPN; Tolerance: N/A; alternate symbols: (); part number: CN2P_TH-TSW-102-07-G-S,E031850,CNTHMHDR1X2L200W98H343; tolerance: N/A
P21 P27 = MOD_RJE73_188_00XXX: User Part Number: UPN; Tolerance: N/A; alternate symbols: (); part number: MOD_RJE73_188_00XXX_TH-RJE73-188-00210,E056744,MRJE73-188-00XXX; tolerance: N/A
P45-P48 = CNTP1P: Tolerance: N/A; User Part Number: UPN; alternate symbols: (); part number: CNTP1P_TH-111-2223-001,E015368,CNEMERSON111-2223-001; tolerance: N/A
Q1 = TRANNMOSFET_V15: User Part Number: UPN; Tolerance: N/A; alternate symbols: (); part number: TRANNMOSFET_V15_SM-DMTH8012LPSQ-13,E045036,POWERDI5060-8; tolerance: N/A
Q2 = TRANMMBT3640: User Part Number: UPN; Tolerance: N/A; alternate symbols: (); part number: TRANMMBT3640_SM-ZXTP25040DFLTA,E018084,SOT23; tolerance: N/A
R1 = RES: User Part Number: UPN; Tolerance: 0.5; alternate symbols: (R0603L); part number: RES_SM-24.9K,E011717,1/16W,0.5,R0603; tolerance: 0.5
R2 = RES: User Part Number: UPN; Tolerance: 1; alternate symbols: (R0402L); part number: RES_SM-31.6K,E019881,1/10W,1,R0402; tolerance: 1
R3 R31 R32 R34 R39 R42-R44 R51 R113 R116 R128 R129 = RES: User Part Number: UPN; Tolerance: 1; alternate symbols: (R0402L,R0402L_ALT); part number: RES_SM-10K,E003751,1/10W,1,R0402; tolerance: 1
R4 R6-R8 R13-R15 R17-R21 R23 R25-R28 R30 R33 R52 R61 R62 R66-R72 R74-R82 R97-R99 R105 R107 R117-R120 R125-R127 R130 R131 R136 R137 = RES: User Part Number: UPN; Tolerance: JUMPER; alternate symbols: (R0402L,R0402L_ALT); part number: RES_SM-0,E003438,1/10W,JUMPER,R0402; tolerance: JUMPER
R5 R24 R29 R46 R100 R101 = RES: User Part Number: UPN; Tolerance: 1; alternate symbols: (R0402L,R0402L_ALT); part number: RES_SM-100K,E003796,1/10W,1,R0402; tolerance: 1
R9-R12 R22 R53-R56 R110 = RES: User Part Number: UPN; Tolerance: 5; alternate symbols: (R0402L); part number: RES_SM-33,E003452,1/10W,5,R0402; tolerance: 5
R16 R35 R36 R47 R112 = RES: User Part Number: UPN; Tolerance: 1; alternate symbols: (R0402L,R0402L_ALT); part number: RES_SM-1K,E003763,1/10W,1,R0402; tolerance: 1
R37 R38 R103 R104 = RES: Tolerance: 1; User Part Number: UPN; alternate symbols: (R1210L); part number: RES_SM-120,E033377,3/4W,1,R1210; tolerance: 1
R40 = RES: User Part Number: UPN; Tolerance: 1; alternate symbols: (R0402L); part number: RES_SM-56.2K,E003771,1/10W,1,R0402; tolerance: 1
R41 = RES: User Part Number: UPN; Tolerance: 1; alternate symbols: (R0402L); part number: RES_SM-10.2K,E019451,1/16W,1,R0402; tolerance: 1
R45 = RES: User Part Number: UPN; Tolerance: 0.5; alternate symbols: (R0805L); part number: RES_SM-12,E003974,1/10W,0.5,R0805; tolerance: 0.5
R48 = RES: User Part Number: UPN; Tolerance: 1; alternate symbols: (R0402L); part number: RES_SM-4.32K,E003776,1/10W,1,R0402; tolerance: 1
R49 = RES: User Part Number: UPN; Tolerance: 1; alternate symbols: (R0402L); part number: RES_SM-470,E042472,1/10W,1,R0402; tolerance: 1
R73 R84 R109 = RES: User Part Number: UPN; Tolerance: 1; alternate symbols: (R0402L); part number: RES_SM-18.2K,E010424,1/10W,1,R0402; tolerance: 1
R83 R114 = RES: User Part Number: UPN; Tolerance: 1; alternate symbols: (R0402L,R0402L_ALT); part number: RES_SM-47K,E008189,1/10W,1,R0402; tolerance: 1
R89-R92 = RES: User Part Number: UPN; Tolerance: 1; alternate symbols: (R0402L); part number: RES_SM-4.75K,E019642,1/16W,1,R0402; tolerance: 1
R93 R94 = RES: User Part Number: UPN; Tolerance: 1; alternate symbols: (R0402L); part number: RES_SM-604,E020998,1/10W,1,R0402; tolerance: 1
R95 R96 = RES: User Part Number: UPN; Tolerance: 1; alternate symbols: (R0402L); part number: RES_SM-49.9K,E004901,1/10W,1,R0402; tolerance: 1
R102 = RES: User Part Number: UPN; Tolerance: 1; alternate symbols: (R1206L); part number: RES_SM-0.05,E035345,1W,1,R1206; tolerance: 1
R106 = RES: User Part Number: UPN; Tolerance: 5; alternate symbols: (R0402L); part number: RES_SM-100,E003443,1/10W,5,R0402; tolerance: 5
R108 = RES: User Part Number: UPN; Tolerance: 5; alternate symbols: (R1206L); part number: RES_SM-0,E010093,1/4W,5,R1206; tolerance: 5
R111 = RES: User Part Number: UPN; Tolerance: 1; alternate symbols: (R0402L); part number: RES_SM-475,E008186,1/10W,1,R0402; tolerance: 1
R115 R135 = RES: User Part Number: UPN; Tolerance: 5; alternate symbols: (R0402L); part number: RES_SM-330,E003462,1/10W,5,R0402; tolerance: 5
R121-R124 = RES: User Part Number: UPN; Tolerance: 5; alternate symbols: (R0402L); part number: RES_SM-5.6,E015599,1/10W,5,R0402; tolerance: 5
R132-R134 R138 R139 = RES: User Part Number: UPN; Tolerance: 1; alternate symbols: (R0402L); part number: RES_SM-2.55K,E014065,1/16W,1,R0402; tolerance: 1
R140 R143 = RES: User Part Number: UPN; Tolerance: 1; alternate symbols: (R1206L); part number: RES_SM-2.74K,E003202,1/4W,1,R1206; tolerance: 1
R141 R142 = RES: User Part Number: UPN; Tolerance: 1; alternate symbols: (R0402L); part number: RES_SM-365,E028356,1/10W,1,R0402; tolerance: 1
U1 U3-U5 = ICIM69D120: User Part Number: UPN; Tolerance: N/A; alternate symbols: (); part number: ICIM69D120_SM-IM69D120V01XTSA1,E059263,LGA-CAV5-1; tolerance: N/A
U2 = ADLT3502: User Part Number: UPN; Tolerance: N/A; alternate symbols: (); part number: ADLT3502_SM-LT3502AEDC#TRMPBF,E035029,DFN8_2X2_PAD1_37X0_64; tolerance: N/A
U7 = AD243XW: Tolerance: N/A; User Part Number: UPN; alternate symbols: (SKTIRONWOOD_SBT-QFN-4022_QFN48_7X7_PAD4_1X4_1,SKTIRONWOOD_SBT-QFN-4022_QFN48_7X7_PAD4_1X4_1_NPM); part number: AD243XW_SM-AD2437,E049687,QFN48_7X7_PAD4_1X4_1; tolerance: N/A
U8 = ADP2360: Tolerance: N/A; User Part Number: UPN; alternate symbols: (); part number: ADP2360_SM-ADP2360ACPZ,E019461,DFN8_3X3_PAD2_44X1_6; tolerance: N/A
U9 = 7408_V3: User Part Number: UPN; Tolerance: N/A; alternate symbols: (); part number: 7408_V3_SM-SN74LVC1G08QDBVRQ1,E040048,SOT23-5L-2; tolerance: N/A
U10 = ADAU1701: Tolerance: N/A; User Part Number: UPN; alternate symbols: (); part number: ADAU1701_SM-ADAU1701JSTZ,E005147,48LQFP; tolerance: N/A
U12 U14 = 741G125: Tolerance: N/A; User Part Number: UPN; alternate symbols: (); part number: 741G125_SM-SN74CB3T1G125DCKR,E063519,SC70-5; tolerance: N/A
U13 = ADA4661_2_V4: Tolerance: N/A; User Part Number: UPN; alternate symbols: (); part number: ADA4661_2_V4_SM-ADA4661-2ACPZ,E020196,QFN8_3X3_PAD2_44X1_7; tolerance: N/A
U15 = 7404_V6: User Part Number: UPN; Tolerance: N/A; alternate symbols: (); part number: 7404_V6_SM-SN74LVC1G04DBVR,E030862,SOT23-5L-2; tolerance: N/A

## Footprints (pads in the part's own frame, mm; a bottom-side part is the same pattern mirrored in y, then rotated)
48LQFP
  rect 0.279x1.397 smd: 1(-2.75,-4.182) 2(-2.25,-4.182) 3(-1.75,-4.182) 4(-1.25,-4.182) 5(-0.75,-4.182) 6(-0.25,-4.182) 7(0.25,-4.182) 8(0.75,-4.182) 9(1.25,-4.182) 10(1.75,-4.182) 11(2.25,-4.182) 12(2.75,-4.182) 25(2.75,4.182) 26(2.25,4.182) 27(1.75,4.182) 28(1.25,4.182) 29(0.75,4.182) 30(0.25,4.182) 31(-0.25,4.182) 32(-0.75,4.182) 33(-1.25,4.182) 34(-1.75,4.182) 35(-2.25,4.182) 36(-2.75,4.182)
  rect 1.397x0.279 smd: 13(4.182,-2.75) 14(4.182,-2.25) 15(4.182,-1.75) 16(4.182,-1.25) 17(4.182,-0.75) 18(4.182,-0.25) 19(4.182,0.25) 20(4.182,0.75) 21(4.182,1.25) 22(4.182,1.75) 23(4.182,2.25) 24(4.182,2.75) 37(-4.182,2.75) 38(-4.182,2.25) 39(-4.182,1.75) 40(-4.182,1.25) 41(-4.182,0.75) 42(-4.182,0.25) 43(-4.182,-0.25) 44(-4.182,-0.75) 45(-4.182,-1.25) 46(-4.182,-1.75) 47(-4.182,-2.25) 48(-4.182,-2.75)
C0402
  rect 0.584x0.66 smd: 1(-0.5,0) 2(0.5,0)
C0402H22
  rect 0.559x0.508 smd: 1(-0.479,0) 2(0.479,0)
C0603
  rect 0.94x0.991 smd: 1(-0.8,0) 2(0.8,0)
C0805
  rect 1.143x1.448 smd: 1(-0.9,0) 2(0.9,0)
C0805H53
  rect 1.295x1.6 smd: 1(-0.953,0) 2(0.953,0)
C0805H60
  rect 1.295x1.6 smd: 1(-0.953,0) 2(0.953,0)
C1206
  rect 1.143x1.803 smd: 1(-1.5,0) 2(1.5,0)
C1206H71
  rect 1.6x2.007 smd: 1(-1.397,0) 2(1.397,0)
C1210-2
  rect 1.092x2.057 smd: 1(-1.646,0) 2(1.646,0)
C1210H110
  rect 1.372x2.794 smd: 1(-1.431,0) 2(1.431,0)
C2220-1
  rect 2.794x5.08 smd: 1(-2.85,0) 2(2.85,0)
CAPSML169W169H217
  rect 2.591x1.6 smd: N(1.796,0) P(-1.796,0)
CAPSML335W335H250
  rect 4.064x1.27 smd: N(3.132,0) P(-3.132,0)
CN3MN2510-6002RB
  rect 1.524x1.524 hole 1.016: 1(0,0)
  round 1.524 hole 1.016: 2(0,2.54) 3(2.54,0) 4(2.54,2.54) 5(5.08,0) 6(5.08,2.54) 7(7.62,0) 8(7.62,2.54) 9(10.16,0) 10(10.16,2.54)
CNCUISJ-3523-SMT
  round 2.972 hole 1.702 unplated: (-3.5,0) (3.5,0)
  rect 2.21x2.794 smd: 1(-4.6,-3.697) 3(-2.6,3.697)
  rect 2.794x2.794 smd: 2(4.8,-3.697)
CNEMERSON111-2223-001
  round 11.43 hole 6.35: 1(0,0)
CNHDR2X6H330
  rect 1.651x1.651 hole 1.143: 1(0,0)
  round 1.651 hole 1.143: 2(0,2.54) 3(2.54,0) 4(2.54,2.54) 5(5.08,0) 6(5.08,2.54) 7(7.62,0) 8(7.62,2.54) 9(10.16,0) 10(10.16,2.54) 11(12.7,0) 12(12.7,2.54)
CNTHMHDR1X2L200W98H343
  rect 1.651x1.651 hole 1.143: 1(0,0)
  round 1.651 hole 1.143: 2(2.54,0)
CNTHMHDR1X3L300W98H343
  rect 1.651x1.651 hole 1.143: 1(0,0)
  round 1.651 hole 1.143: 2(2.54,0) 3(5.08,0)
CNTHMHDR2X12L1200W200H330
  rect 1.651x1.651 hole 1.143: 1(0,0)
  round 1.651 hole 1.143: 2(0,2.54) 3(2.54,0) 4(2.54,2.54) 5(5.08,0) 6(5.08,2.54) 7(7.62,0) 8(7.62,2.54) 9(10.16,0) 10(10.16,2.54) 11(12.7,0) 12(12.7,2.54) 13(15.24,0) 14(15.24,2.54) 15(17.78,0) 16(17.78,2.54) 17(20.32,0) 18(20.32,2.54) 19(22.86,0) 20(22.86,2.54) 21(25.4,0) 22(25.4,2.54) 23(27.94,0) 24(27.94,2.54)
CPLSMSQ169H240
  rect 2.489x1.6 smd: N(1.745,0) P(-1.745,0)
CPLSMSQ409H413
  rect 4.496x2.489 smd: N(3.748,0) P(-3.748,0)
DFN8_2X2_PAD1_37X0_64
  oval 0.254x0.737 smd: 1(-0.675,-0.888) 2(-0.225,-0.888) 3(0.225,-0.888) 4(0.675,-0.888) 5(0.675,0.888) 6(0.225,0.888) 7(-0.225,0.888) 8(-0.675,0.888)
  rect 1.372x0.635 smd: PAD(0,0)
DFN8_3X3_PAD2_44X1_6
  oval 0.356x0.787 smd: 1(-0.975,-1.5) 2(-0.325,-1.5) 3(0.325,-1.5) 4(0.975,-1.5) 5(0.975,1.5) 6(0.325,1.5) 7(-0.325,1.5) 8(-0.975,1.5)
  rect 2.438x1.6 smd: PAD(0,0)
FLSML154W98H98
  rect 1.041x0.61 smd: 1(-1.521,0.505) 2(-1.521,-0.505) 3(1.521,-0.505) 4(1.521,0.505)
INDSUMCDRH8D43
  rect 2.032x2.794 smd: 1(-4.034,0) 2(4.034,0)
L0402-3
  rect 0.457x0.508 smd: 1(-0.479,0) 2(0.479,0)
L0603
  rect 0.94x0.991 smd: 1(-0.8,0) 2(0.8,0)
L0603-2
  rect 0.991x1.245 smd: 1(-0.787,0) 2(0.787,0)
L0805H57
  rect 0.914x1.372 smd: 1(-0.902,0) 2(0.902,0)
LED0805
  rect 1.245x1.092 smd: A(1.172,0) C(-1.172,0)
LGA-CAV5-1
  round 0.533 hole 0.406 unplated: (0,-0.78)
  rect 0.762x0.457 smd: 1(0.85,1.4) 2(0.85,0.7) 3(-0.85,1.4) 4(-0.85,0.7)
  round 0 smd: 5(0,-0.1)
LSML213W201H59
  rect 1.397x2.794 smd: 1(-2.199,0) 2(2.199,0)
LSMSQ228H118_A
  custom 0.552x0.552 smd: 1(-2.682,0) 2(2.682,0)
LXT0805
  rect 1.194x1.194 smd: A(1.041,0) C(-1.041,0)
MRJE73-188-00XXX
  round 2.311 hole 1.803 unplated: (-2.17,-0.33) (9.31,-0.33)
  rect 1.397x1.397 hole 0.889: 1(0,0)
  round 1.397 hole 0.889: 2(1.02,-1.78) 3(2.04,0) 4(3.06,-1.78) 5(4.08,0) 6(5.1,-1.78) 7(6.12,0) 8(7.14,-1.78)
  round 1.6 hole 1.092: 9(-3.44,3.27) 10(-0.9,3.27) 11(8.04,3.27) 12(10.58,3.27)
  oval 1.295x2.515 hole 0.787x2.007: 13(-4.43,-4.68) 14(11.57,-4.68)
POWERDI5060-8
  rect 0.61x1.27 smd: 1(-1.905,-2.67) 2(-0.635,-2.67) 3(0.635,-2.67) 4(1.905,-2.67)
  custom 1.13x1.13 smd: 5(1.905,2.797)
  round 0.127 smd: 6(0.635,2.67) 7(-0.635,2.67) 8(-1.905,2.67)
QFN8_3X3_PAD2_44X1_7
  oval 0.305x0.914 smd: 1(-0.75,-1.557) 2(-0.25,-1.557) 3(0.25,-1.557) 4(0.75,-1.557) 5(0.75,1.557) 6(0.25,1.557) 7(-0.25,1.557) 8(-0.75,1.557)
  rect 2.438x1.702 smd: PAD(0,0)
QFN24_4X4_PAD2_4X2_4
  oval 0.279x0.737 smd: 1(-1.25,-1.883) 2(-0.75,-1.883) 3(-0.25,-1.883) 4(0.25,-1.883) 5(0.75,-1.883) 6(1.25,-1.883) 13(1.25,1.883) 14(0.75,1.883) 15(0.25,1.883) 16(-0.25,1.883) 17(-0.75,1.883) 18(-1.25,1.883)
  oval 0.737x0.279 smd: 7(1.883,-1.25) 8(1.883,-0.75) 9(1.883,-0.25) 10(1.883,0.25) 11(1.883,0.75) 12(1.883,1.25) 19(-1.883,1.25) 20(-1.883,0.75) 21(-1.883,0.25) 22(-1.883,-0.25) 23(-1.883,-0.75) 24(-1.883,-1.25)
  rect 2.388x2.388 smd: PAD(0,0)
QFN48_7X7_PAD4_1X4_1
  round 2.718 hole 1.702 unplated: (-4.863,4.863) (-4.863,-4.863) (4.863,4.863) (4.863,-4.863)
  round 1.092 hole 0.838 unplated: (-2.863,4.863) (1.863,-4.863)
  oval 0.305x0.889 smd: 1(-2.75,-3.2) 2(-2.25,-3.2) 3(-1.75,-3.2) 4(-1.25,-3.2) 5(-0.75,-3.2) 6(-0.25,-3.2) 7(0.25,-3.2) 8(0.75,-3.2) 9(1.25,-3.2) 10(1.75,-3.2) 11(2.25,-3.2) 12(2.75,-3.2) 25(2.75,3.7) 26(2.25,3.7) 27(1.75,3.7) 28(1.25,3.7) 29(0.75,3.7) 30(0.25,3.7) 31(-0.25,3.7) 32(-0.75,3.7) 33(-1.25,3.7) 34(-1.75,3.7) 35(-2.25,3.7) 36(-2.75,3.7)
  oval 0.889x0.305 smd: 13(3.45,-2.5) 14(3.45,-2) 15(3.45,-1.5) 16(3.45,-1) 17(3.45,-0.5) 18(3.45,0) 19(3.45,0.5) 20(3.45,1) 21(3.45,1.5) 22(3.45,2) 23(3.45,2.5) 24(3.45,3) 37(-3.45,3) 38(-3.45,2.5) 39(-3.45,2) 40(-3.45,1.5) 41(-3.45,1) 42(-3.45,0.5) 43(-3.45,0) 44(-3.45,-0.5) 45(-3.45,-1) 46(-3.45,-1.5) 47(-3.45,-2) 48(-3.45,-2.5)
  rect 4.089x4.089 smd: PAD(0,0.25)
R0402
  rect 0.635x0.737 smd: 1(-0.5,0) 2(0.5,0)
R0603
  rect 0.787x0.991 smd: 1(-0.85,0) 2(0.85,0)
R0805
  rect 1.041x1.397 smd: 1(-0.95,0) 2(0.95,0)
R1206
  rect 1.041x1.753 smd: 1(-1.5,0) 2(1.5,0)
R1210
  rect 1.575x2.692 smd: 1(-1.397,0) 2(1.397,0)
SC70-5
  rect 0.406x0.813 smd: 1(-0.65,-0.89) 2(0,-0.89) 3(0.65,-0.89) 4(0.65,0.89) 5(-0.65,0.89)
SMA
  rect 2.032x2.032 smd: A(1.994,0) C(-1.994,0)
SO8
  rect 0.61x2.184 smd: 1(-1.905,-2.54) 2(-0.635,-2.54) 3(0.635,-2.54) 4(1.905,-2.54) 5(1.905,2.54) 6(0.635,2.54) 7(-0.635,2.54) 8(-1.905,2.54)
SOD123F
  rect 1.194x1.194 smd: A(1.403,0) C(-1.403,0)
SOD123FL
  rect 0.914x1.219 smd: A(1.638,0) C(-1.638,0)
SOT23
  rect 1.016x1.397 smd: 1(-0.94,-1.118) 2(0.94,-1.118) 3(0,1.118)
SOT23-5L-2
  rect 0.61x1.194 smd: 1(-0.95,-1.15) 2(0,-1.15) 3(0.95,-1.15) 4(0.95,1.15) 5(-0.95,1.15)
TPC65D45
  round 1.651 hole 1.143: 1(0,0)
unnamed#2
  round 4.445 hole 3.175 unplated: (0,0)

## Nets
DGND: A1.1 A1.2 A1.3 A1.4 A2.11 A2.15 A2.21 A2.PAD A3.4 A3.7(WC_N) C1.1 C2.2(N2) C3.1 C4.1 C5.1 C6.1 C7.2(N2) C8.1 C9.1 C10.1 C11.2(N2) C12.1 C13.2(N2) C14.2(N2) C15.2(N2) C16.2(N2) C17.1 C18.1 C19.2(N2) C20.2(N2) C21.2(N2) C22.1 C23.1 C25.1 C27.1 C29.2(N2) C30.1 C31.2(N2) C32.2(N2) C35.1 C36.1 C38.1 C39.1 C40.1 C41.1 C42.1 C43.1 C44.2(N2) C48.1 C51.2(N2) C53.2(N2) C55.2(N2) C56.2(N2) C62.2(N2) C63.2(N2) C64.2(N2) C65.2(N2) C66.1 C67.1 C69.2(N2) C73.2(N2) C74.2(N2) C75.2(N2) C78.1 C79.2(N2) C80.2(N2) C83.2(N2) C84.2(N2) C85.1 C86.1 C87.2(N2) C89.1 C90.2(N2) C91.N(N2) C92.1 C93.1 C94.2(N2) C96.N(N2) C97.N(N2) C98.2(N2) C99.2(N2) C100.2(N2) C101.2(N2) C102.2(N2) C103.2(N2) C104.2(N2) C105.2(N2) C106.N(N2) C107.2(N2) C109.2(N2) C111.2(N2) C112.2(N2) C113.2(N2) C116.2(N2) C117.2(N2) C120.2(N2) C123.2(N2) C124.2(N2) C125.1 C126.2(N2) C127.1 C128.2(N2) C129.1 C130.2(N2) C131.1 C132.1 C133.2(N2) C134.2(N2) C135.2(N2) D4.A(P) D7.A(P) DS1.C DS4.C DS5.C E12.1 E13.1 E14.1 E15.1 L3.2(N2) L12.2(N2) P1.2 P1.4 P1.6 P1.8 P1.10 P1.12 P1.14 P1.16 P1.18(N9) P1.20 P1.22 P1.23 P1.24 P2.10 P5.2 P5.4 P5.6 P5.8 P5.10 P5.12 P7.1 P13.1(N1) P18.2(N2) P20.1 P21.1 P21.6 P21.8 P21.10 P27.1 P27.6 P27.8 P39.1(N1) P40.1(N1) P41.1(N1) P42.1(N1) R3.1 R5.1 R27.1 R28.1 R31.1 R32.1 R35.1 R36.1 R41.1 R42.1 R45.2(N2) R46.1 R48.1 R49.1 R83.2(N2) R95.2(N2) R96.2(N2) R100.1 R101.1 R108.1 R109.1 R121.1 R123.1 R130.1 R131.1 R140.2(N2) R141.1 R143.2(N2) TP10.1(N1) TP11.1(N1) U1.5 U2.5 U2.PAD U3.4 U3.5 U4.5 U5.4 U5.5 U7.1 U7.4 U7.10 U7.20 U7.26(VSS) U7.30 U7.32 U7.38 U7.44 U7.PAD U8.6 U8.PAD U9.3 U10.1 U10.7 U10.12 U10.20 U10.25 U10.30 U10.33 U10.37 U10.38 U10.42 U12.3 U13.4(V-) U13.PAD U14.3 U15.3
PGND: E14.2(N2) E15.2(N2) P21.13 P21.14(SH2) R108.2(N2) TP4.1(N1)
PGND1: C87.1 E12.2(N2) E13.2(N2) P27.13 P27.14(SH2) TP3.1(N1)
VDD_3V3: C73.1 C96.P C97.P C99.1 C101.1 C103.1 C105.1 C110.2(N2) C112.1 C132.2(N2) C133.1 C134.1 C135.1 E4.1 E9.1 E10.2(N2) E16.2(N2) Q2.2(E) R16.2(N2) R39.2(N2) R44.2(N2) R49.2(N2) R51.2(N2) R105.2(N2) R111.2(N2) R112.2(N2) R113.2(N2) R114.1 R115.1 R116.2(N2) R129.2(N2) R132.2(N2) R133.2(N2) R134.2(N2) TP1.1(N1) U9.5 U10.18 U10.34 U10.36 U10.39 U10.48 U12.5(VCC) U13.8 U14.5(VCC) U15.5(VCC)
VDD_5V: C41.2(N2) C42.2(N2) D1.C D7.C L13.2(N2) R46.2(N2) R107.2(N2) R142.1 TP2.1(N1)
VIN0: R84.2(N2) U10.4
VIN1: R73.2(N2) U10.2
AD243X_AN: C24.1 L1.1 U7.28
AD243X_AP: C24.2(N2) L2.1 U7.29
AD243X_BCLK: C6.2(N2) P16.1 R10.1 R67.2(N2) R126.1 R127.1
AD243X_BN: C88.1 L11.1 U7.34
AD243X_BP: C88.2(N2) L10.1 U7.33
AD243X_GPIO4: R13.1 U7.22
AD243X_IOVDD: C15.1 C16.1 R18.1 R34.2(N2) R43.1 R128.2(N2) R138.2(N2) R139.2(N2) U7.11 U7.21
AD243X_IRQ: DS2.A(P) R14.2(N2) R117.2(N2) TP9.1(N1)
AD243X_ISENSEP: Q1.5 Q1.6 Q1.7 Q1.8 R102.1 U7.42
AD243X_MISO: R21.2(N2) R79.2(N2)
AD243X_MOSI: R22.2(N2) R81.2(N2)
AD243X_RESET: C17.2(N2) R43.2(N2) R76.2(N2) U7.25
AD243X_SCK: R23.2(N2) R80.2(N2)
AD243X_SCL: R20.2(N2) R25.2(N2) R137.1 R138.1
AD243X_SDA: R19.2(N2) R30.2(N2) R136.1 R139.1
AD243X_SIO2: R8.2(N2) R125.2(N2) U7.7
AD243X_SWP: R98.1 U7.41
AD243X_SYNC: C8.2(N2) R9.1 R69.2(N2) R120.1 U10.8 U10.16
AD243X_VBUS: A2.10 A2.14 A2.20(VCCP2) C1.2(N2) C25.2(N2) C91.P C92.2(N2) C116.1 C117.1 C125.2(N2) D2.C P27.2 P27.3 P27.7 P27.11 R1.2(N2) R24.2(N2) R102.2(N2) U2.1(VIN) U7.43 U8.8(VIN)
AD243X_VIN: C12.2(N2) C13.1 C14.1 D6.C P8.1(N1) U7.46
AD243X_VOUT2: C18.2(N2) C19.1 DS3.A(P) E17.1 P15.1(N1) R18.2(N2) R29.2(N2) R33.1 U7.45
AD243X_VSENSEP: R99.1 U7.40
ADAU1701_BCLK: R126.2(N2) U10.9 U10.19
ADAU1701_I2C_EN*: R134.1 U9.4(Y) U12.1 U14.1 U15.2
ADAU1701_SCL: R61.2(N2) R133.1 U10.23 U14.2
ADAU1701_SDA: R62.2(N2) R132.1 U10.22 U12.2
ADAU1701_SDATA_IN: C3.2(N2) R12.1 R68.2(N2) U10.11
ADAU1701_SDATA_OUT: P4.3(N3) R66.2(N2) R110.1
ADAU1701_SELFBOOT: P22.2(N2) R5.2(N2) U9.2 U10.6
ADAU1701_WP*: A1.7(WC_N) P18.1 R39.1 U10.21
ADP2360_PG: R15.1 R29.1 U8.2
ADR1/SPISSO: P14.1(N1) R13.2(N2) R31.2(N2) R82.2(N2) R128.1
ADR2/IO2/MCLK: A2.1 P17.1(N1) R32.2(N2) R34.1 R70.2(N2) U7.23 U10.32
BD28623_BCLK: R119.1 R127.2(N2)
BD28623_MUTEX: A2.7 P23.3(N3) R42.2(N2)
BD28623_SDATA_IN: C5.2(N2) R11.1 R75.2(N2) R118.1
LT3502_FB: R2.2(N2) R3.2(N2) U2.3
MP1: P5.1 R129.1 U9.1 U10.10
MP2: P5.3 U10.29
MP3: P5.5 U10.28
MP7: P5.7 U10.14
MP8: P5.9(N9) U10.27
MP9: P5.11 U10.26
PDM_CLK: P16.2(N2) R52.2(N2) R72.2(N2)
PDM_DATA0: C67.2(N2) P4.1 R53.2(N2) R56.2(N2)
PDM_DATA1: C66.2(N2) P23.1 R54.2(N2) R55.2(N2) R74.2(N2)
SPI_EEPROM_CS: R8.1 R71.2(N2)
UNNAMED_2_AD243XW_I5_ACM: C85.2(N2) C86.2(N2) U7.27
UNNAMED_2_AD243XW_I5_BCLK: P11.1(N1) R10.2(N2) U7.9
UNNAMED_2_AD243XW_I5_BCM: C43.2(N2) C89.2(N2) U7.35
UNNAMED_2_AD243XW_I5_DVDD1: C2.1 C4.2(N2) P9.1(N1) R4.1 U7.2 U7.3
UNNAMED_2_AD243XW_I5_GPIO7: R15.2(N2) U7.14
UNNAMED_2_AD243XW_I5_IRQ: R14.1 U7.24
UNNAMED_2_AD243XW_I5_ISENSEN: R100.2(N2) U7.36 U7.37
UNNAMED_2_AD243XW_I5_MISO: R21.1 U7.17
UNNAMED_2_AD243XW_I5_MOSI: R22.1 U7.18
UNNAMED_2_AD243XW_I5_PLVDD: C7.1 C9.2(N2) C10.2(N2) C11.1 P6.1(N1) R4.2(N2) U7.47 U7.48
UNNAMED_2_AD243XW_I5_SCK: R23.1 U7.19
UNNAMED_2_AD243XW_I5_SCL: R20.1 U7.16
UNNAMED_2_AD243XW_I5_SDA: R19.1 U7.15
UNNAMED_2_AD243XW_I5_SIO0: R6.2(N2) U7.5
UNNAMED_2_AD243XW_I5_SIO1: R7.2(N2) U7.6
UNNAMED_2_AD243XW_I5_SIO3: R11.2(N2) U7.12
UNNAMED_2_AD243XW_I5_SIO4: R12.2(N2) U7.13
UNNAMED_2_AD243XW_I5_SWN: R101.2(N2) U7.39
UNNAMED_2_AD243XW_I5_SYNC: P12.1(N1) R9.2(N2) U7.8
UNNAMED_2_AD243XW_I5_TRXVDD: C20.1 C21.1 C22.2(N2) C23.2(N2) P10.1(N1) R33.2(N2) U7.31
UNNAMED_2_CAP_I160_N1: C79.1 E10.1 P1.1
UNNAMED_2_CN3P_I189_N2: P4.2 R6.1
UNNAMED_2_CN3P_I190_N2: P23.2 R7.1
UNNAMED_2_CN24PODDEVEN_I191_N2: P1.3 R66.1
UNNAMED_2_CN24PODDEVEN_I191_N3: P1.5 R67.1
UNNAMED_2_CN24PODDEVEN_I191_N4: P1.7 R68.1
UNNAMED_2_CN24PODDEVEN_I191_N5: P1.9 R69.1
UNNAMED_2_CN24PODDEVEN_I191_N6: P1.11 R70.1
UNNAMED_2_CN24PODDEVEN_I191_N7: P1.13 R71.1
UNNAMED_2_CN24PODDEVEN_I191_N8: P1.15 R72.1
UNNAMED_2_CN24PODDEVEN_I191_N9: P1.17 R74.1
UNNAMED_2_CN24PODDEVEN_I191_N10: P1.19 R75.1
UNNAMED_2_CN24PODDEVEN_I191_N11: P1.21 R76.1
UNNAMED_2_DIOLED_I111_N: DS2.C R35.2(N2)
UNNAMED_2_DIOLED_I114_N: DS3.C R36.2(N2)
UNNAMED_5_ADLT3502_I61_BD: C35.2(N2) C36.2(N2) C131.2(N2) E16.1 L18.2(N2) R2.1 U2.2
UNNAMED_5_ADLT3502_I61_BOOST: C28.2(N2) U2.7
UNNAMED_5_ADLT3502_I61_DA: D5.A(P) U2.6
UNNAMED_5_ADLT3502_I61_SHDNN: R1.1 R48.2(N2) U2.4
UNNAMED_5_ADLT3502_I61_SW: C28.1 D5.C L18.1 U2.8
UNNAMED_5_ADP2360_I29_EN: R24.1 U8.1
UNNAMED_5_ADP2360_I29_FB: C37.1 R40.1 R41.2(N2) U8.4
UNNAMED_5_ADP2360_I29_ITH: R27.2(N2) U8.3
UNNAMED_5_ADP2360_I29_SS: C27.2(N2) U8.5
UNNAMED_5_ADP2360_I29_SW: L6.1 U8.7
UNNAMED_5_CAP_I36_N2: C37.2(N2) C38.2(N2) C39.2(N2) E1.1 L6.2(N2) R40.2(N2)
UNNAMED_5_CAP_I38_N2: C40.2(N2) D1.A(P) E1.2(N2) R47.2(N2)
UNNAMED_5_DIOLED_I72_P: DS1.A(P) R16.1
UNNAMED_5_DIOLED_I78_P: DS5.A(P) R47.1
UNNAMED_6_ADA46612V4_I99_: C77.2(N2) C82.P U13.6 U13.7
UNNAMED_6_ADA46612V4_I99__1: C75.1 R92.2(N2) U13.5
UNNAMED_6_ADA46612V4_I100_: C76.2(N2) C81.P U13.1 U13.2
UNNAMED_6_ADA46612V4_I100__1: C74.1 R91.2(N2) U13.3
UNNAMED_6_CAP_I60_N1: C84.1 P20.2 R94.2(N2) R96.1
UNNAMED_6_CAP_I64_N1: C77.1 R90.2(N2) R92.1
UNNAMED_6_CAP_I67_N1: C76.1 R89.2(N2) R91.1
UNNAMED_6_CAP_I74_N1: C83.1 P20.3(N3) R93.2(N2) R95.1
UNNAMED_6_CAP_I86_N1: C55.1 C57.P E2.2(N2)
UNNAMED_6_CAP_I91_N1: C56.1 C58.P E3.2(N2)
UNNAMED_6_CAPP_I68_N2: C82.N(N2) R94.1
UNNAMED_6_CAPP_I69_N2: C81.N(N2) R93.1
UNNAMED_6_CAPP_I103_N2: C57.N(N2) R73.1
UNNAMED_6_CAPP_I104_N2: C58.N(N2) R84.1
UNNAMED_6_CN3P_I18_N2: E3.1 P7.2
UNNAMED_6_CN3P_I18_N3: E2.1 P7.3(N3)
UNNAMED_15_CAP_I9_N2: C30.2(N2) FL1.1 L2.2(N2)
UNNAMED_15_CAP_I13_N1: C29.1 FL1.2 L1.2(N2)
UNNAMED_15_CAP_I18_N1: C31.1 C32.1 R37.2(N2) R38.2(N2)
UNNAMED_15_CAP_I95_N1: C33.1 FL1.3 R37.1
UNNAMED_15_CAP_I95_N2: C33.2(N2) L3.1 P27.4
UNNAMED_15_CAP_I96_N1: C34.1 FL1.4(N4) R38.1
UNNAMED_15_CAP_I96_N2: C34.2(N2) L4.1 P27.5
UNNAMED_15_DIOSCHOTTKY_I87_P: D6.A(P) L4.2(N2) P27.9
UNNAMED_15_MODRJE7318800XXX_I126_LED1C: P27.12 R140.1
UNNAMED_15_MODRJE7318800XXX_I126_LED2C: P27.10 R141.2(N2)
UNNAMED_16_CAP_I13_N1: C44.1 FL2.1 L11.2(N2)
UNNAMED_16_CAP_I15_N2: C48.2(N2) FL2.2 L10.2(N2)
UNNAMED_16_CAP_I17_N1: C93.2(N2) C94.1 R103.1 R104.1
UNNAMED_16_CAP_I25_N1: C46.1 C50.1 C53.1 D2.A(P) D3.C D4.C P21.2 P21.3 P21.7 P21.11 Q1.1 Q1.2 Q1.3(S3) R99.2(N2)
UNNAMED_16_CAP_I25_N2: C50.2(N2) Q1.4 R98.2(N2)
UNNAMED_16_CAP_I58_N2: C46.2(N2) R45.1
UNNAMED_16_CAP_I69_N1: C95.1 FL2.3 R103.2(N2)
UNNAMED_16_CAP_I69_N2: C95.2(N2) L12.1 P21.4
UNNAMED_16_CAP_I70_N1: C61.1 FL2.4(N4) R104.2(N2)
UNNAMED_16_CAP_I70_N2: C61.2(N2) L13.1 P21.5
UNNAMED_16_DIOSCHOTTKY_I60_P: D3.A(P) R106.1
UNNAMED_16_MODRJE7318800XXX_I93_LED1C: P21.12 R143.1
UNNAMED_16_MODRJE7318800XXX_I93_LED2A: P21.9 R142.2(N2)
UNNAMED_16_RES_I51_N2: R105.1 R106.2(N2) R107.1
UNNAMED_17_CAP_I107_N1: A3.8 C51.1 E17.2(N2) R17.2(N2) R26.2(N2) R97.2(N2)
UNNAMED_17_CAP_I108_N1: C62.1 C63.1 C64.1 C65.1 E4.2(N2) U1.2(VDD) U1.4 U3.2(VDD) U4.2(VDD) U4.4 U5.2(VDD)
UNNAMED_17_CAP_I156_N1: A1.8 C69.1 E9.2(N2)
UNNAMED_17_ICIM69D120_I169_DATA: R54.1 U1.1
UNNAMED_17_ICIM69D120_I170_CLOCK: R52.1 U1.3 U3.3 U4.3 U5.3
UNNAMED_17_ICIM69D120_I170_DATA: R55.1 U3.1
UNNAMED_17_ICIM69D120_I171_DATA: R56.1 U4.1
UNNAMED_17_ICIM69D120_I172_DATA: R53.1 U5.1
UNNAMED_17_ICM24512_I103_E0: A3.1 R17.1 R131.2(N2)
UNNAMED_17_ICM24512_I103_E1: A3.2 R97.1 R130.2(N2)
UNNAMED_17_ICM24512_I103_E2: A3.3 R26.1 R28.2(N2)
UNNAMED_17_ICM24512_I103_SCL: A3.6 R25.1
UNNAMED_17_ICM24512_I103_SDA: A3.5 R30.1
